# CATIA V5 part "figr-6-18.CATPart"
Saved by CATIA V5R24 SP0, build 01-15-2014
Part number: Part1
Bounding box of the stored display mesh (mm): x 0 to 150, y -70 to 70, z -150 to 69.804
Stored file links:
  D:\KAVITA\CATIA V5-6R2014 Project_ Kavita\CATIA V5-6R2014_partfiles\Partfiles\c06_catia_v5-6r2014_prt\figr-6-18.CATPart
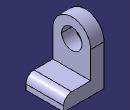
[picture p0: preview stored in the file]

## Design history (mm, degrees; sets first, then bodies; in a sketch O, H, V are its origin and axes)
Body1 (main body)
  Sketch1 on yz-plane, origin (0, 0, 0), H (0, 1, 0), V (0, 0, 1)
    arc A1 centre (0, 0) radius 70 from (70, 0) to (-70, 0) ccw
    point P1 (70, 0)
    point P2 (-70, 0)
    line L1 (-70, 0) -> (-70, -150)
    line L2 (-70, -150) -> (70, -150)
    line L3 (70, -150) -> (70, 0)
    circle A2 centre (0, 0) radius 37.5
    radius A1 = 70
    radius A2 = 37.5
    distance O L2 = 150
    coincidence: P1 H, P2 H
    tangency: L1 A1, L3 A1
    horizontal: L2 H
  Pad1: profile Sketch1, direction (1, 0, 0), length 50
  Sketch2 on face of Pad1, origin (50, 0, 0), H (0, 1, 0), V (0, 0, 1)
    line L1 (-70, -150) -> (70, -150)
    line L2 (70, -150) -> (70, -100)
    line L3 (70, -100) -> (-70, -100)
    line L4 (-70, -100) -> (-70, -150)
    reference projected line E1 (-70, -150) -> (70, -150) from edge [face of Pad1 | face of Pad1]
    reference projected line E2 (-70, 0) -> (-70, -150) from edge [face of Pad1 | face of Pad1]
    reference projected line E3 (70, -150) -> (70, 0) from edge [face of Pad1 | face of Pad1]
    length L2 = 50
    horizontal: L1 H, L3 H
    vertical: L2 V, L4 V
    coincidence: L1 E1, E2 L4, L2 E3
  Pad2: profile Sketch2, direction (1, 0, 0), length 100
  Fillet1: radius 30, on edge [face of Pad2 | face of Pad2]
  Sketch3 on face of Pad1, origin (50, 0, 0), H (0, 1, 0), V (0, 0, 1)
    point P1 (45.5554, 53.148)
    reference projected arc E1 centre (0, 0) radius 70 from (70, 0) to (-70, 0) ccw from edge [face of Pad1 | face of Pad1]
    coincidence: P1 E1
  Sketch4 on face of Pad2, origin (0, 0, -100), H (1, 0, 0), V (0, 1, 0)
    point P1 (110, 20)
